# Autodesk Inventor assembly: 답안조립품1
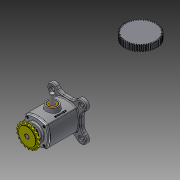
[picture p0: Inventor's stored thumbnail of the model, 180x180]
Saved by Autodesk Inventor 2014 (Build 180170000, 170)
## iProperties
Created: 2016-05
Part Number: 답안조립품1
Document SubType Name: Assembly
Designer: Administrator
Author: Administrator
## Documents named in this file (12)
- C:\Users\Administrator\Desktop\460507V1015\답안조립품1.iam
- C:\Users\Administrator\Desktop\460507V1015\본체.ipt
- C:\Users\Administrator\Desktop\460507V1015\M4x0.7x12.ipt
- C:\Users\Administrator\Desktop\460507V1015\베어링-6203.ipt
- C:\Users\Administrator\Desktop\460507V1015\부시.ipt
- C:\Users\Administrator\Desktop\460507V1015\스퍼기어.ipt
- C:\Users\Administrator\Desktop\460507V1015\스프로킷.ipt
- C:\Users\Administrator\Desktop\460507V1015\슬라이더.ipt
- C:\Users\Administrator\Desktop\460507V1015\오일실.ipt
- C:\Users\Administrator\Desktop\460507V1015\커버.ipt
- C:\Users\Administrator\Desktop\460507V1015\키5x5.ipt
- C:\Users\Administrator\Desktop\460507V1015\편심축.ipt
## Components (8 placed, 1 different names)
1. M4x0.7x12:2
2. M4x0.7x12:3
3. M4x0.7x12:4
4. M4x0.7x12:5
5. M4x0.7x12:1
6. M4x0.7x12:6
7. M4x0.7x12:7
8. M4x0.7x12:8
